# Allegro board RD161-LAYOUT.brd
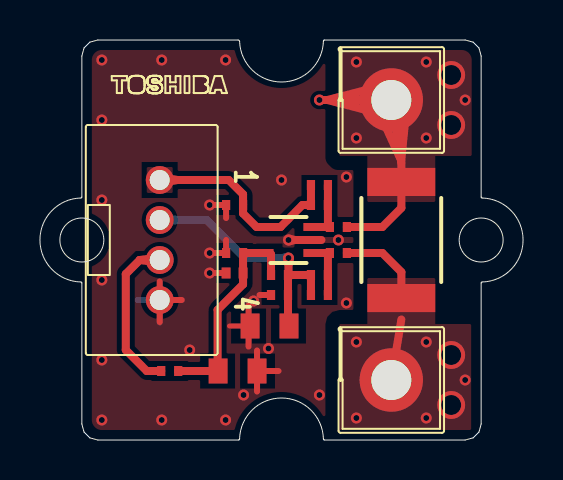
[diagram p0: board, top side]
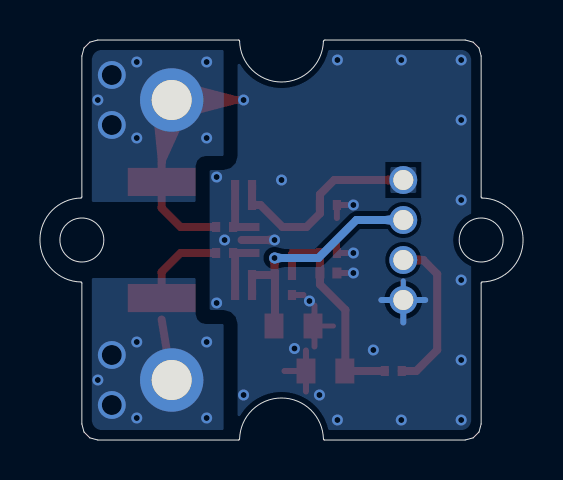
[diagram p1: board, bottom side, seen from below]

Outline 24.2 x 20 mm; copper layers: TOP, BOTTOM. Coordinates in mm from the lower left corner of the outline.
Outline path: circle c2.1,10 r1.1 ; circle c22.1,10 r1.1 ; 2.05,12.1 2.09,12.11 2.1,12.15 2.1,19.2 2.21,19.6 2.5,19.89 2.9,20 9.92,20 9.98,19.98 10,19.93 arc(12.11,17.9) 14.2,19.95 14.21,19.99 14.25,20 21.3,20 21.7,19.89 21.99,19.6 22.1,19.2 22.1,12.15 22.11,12.11 22.15,12.1 arc(24.2,10) 22.15,7.9 22.11,7.89 22.1,7.85 22.1,0.8 21.99,0.4 21.7,0.11 21.3,0 14.25,0 14.21,0.01 14.2,0.05 arc(12.1,2.1) 10,0.05 9.99,0.01 9.95,0 2.9,0 2.5,0.11 2.21,0.4 2.1,0.8 2.1,7.85 2.09,7.89 2.05,7.9 arc(0,10) 2.05,12.1

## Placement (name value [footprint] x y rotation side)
C1  -  [KC00050ACP]  14 7.25 180 top
C4  -  [KC01320AKP]  9.75 8.35 180 top
C5  -  [KC00050ACP]  9.75 9.35 180 top
C12  -  [KC00060ATP]  9.9 3.45 0 top
C13  -  [KC00050ACP]  14 12.75 180 top
C14  -  [KC00060ATP]  11.5 5.7 180 top
CN1  -  [CUP10060ATP]  6 13 270 top
NOREF  -  []  2.75 16.5 0 top
R1  -  [DR824K0ACP]  14 8.25 180 top
R9  -  [KC00050ACP]  6.5 3.45 180 top
R10  -  [R8100A]  18.1 10 90 top
R11  -  [DR824K0ACP]  14.95 9.35 180 top
R12  -  [DR824K0ACP]  14.95 10.65 180 top
R13  -  [DR824K0ACP]  14 11.75 180 top
R14  -  [DR824K0ACP]  12 7.25 180 top
R15  -  [DR824K0ACP]  12 8.25 180 top
R16  -  [KC00050ACP]  9.75 11.75 0 top
TP1  -  [DE051A]  17.6 3 0 top
TP2  -  [DE051A]  17.6 17 0 top
U1  -  [MM00380ACP]  12.45 10 90 top

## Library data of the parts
C1 C13 = GDM030000385: alternate symbols: (T:KC00050ACP;B:KC00050BCP)
C4 = GAS030000012: alternate symbols: (T:KC01320AKP;B:KC01320BKP)
C5 = GDM030002515: alternate symbols: (T:KC00050ACP;B:KC00050BCP)
C12 C14 = GDM030002136: alternate symbols: (T:KC00060ATP;B:KC00060BTP)
CN1 = K22S001P: alternate symbols: (T:CUP10060ATP;B:CUP10060BTP)
R1 R13 = G36010118152: alternate symbols: (T:DR824K0ACP;B:DR824K0BCP)
R9 R16 = GDM010000374: alternate symbols: (T:KC00050ACP;B:KC00050BCP)
R10 = K0100130: alternate symbols: (T:R8100A;B:R9100A)
R11 R12 = GDM010000088: alternate symbols: (T:DR824K0ACP;B:DR824K0BCP)
R14 = G36010118534: alternate symbols: (T:DR824K0ACP;B:DR824K0BCP)
R15 = G36010118602: alternate symbols: (T:DR824K0ACP;B:DR824K0BCP)
TP1 TP2 = ZS_DE051A: alternate symbols: (T:DE051A;B:NO_DE051A)
U1 = K47S002A: alternate symbols: (T:MM00380ACP;B:MM00380BCP)

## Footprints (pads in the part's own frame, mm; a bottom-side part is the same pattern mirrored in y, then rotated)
CUP10060ATP
  round 1.397 hole 1: 1(0,0) 2(2,0) 3(4,0) 4(6,0)
DE051A
  round 3.175 hole 2: 1(0,0)
DR824K0ACP
  rect 0.41x0.5 smd: 1(-0.425,0) 2(0.425,0)
KC00050ACP
  rect 0.41x0.5 smd: 1(-0.425,0) 2(0.425,0)
KC00060ATP
  rect 0.95x1.25 smd: 1(-0.975,0) 2(0.975,0)
KC01320AKP
  rect 0.45x0.55 smd: 1(-0.425,0) 2(0.425,0)
MM00380ACP
  rect 0.4x0.55 smd: 1(-0.65,-1.025) 2(0,-1.025) 3(0.65,-1.025) 4(0.65,1.025) 5(-0.65,1.025)
R8100A
  rect 1.405x3.4 smd: 1(-2.902,0) 2(2.902,0)

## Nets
GND: C4.2(TP-1) C5.2(TP-1) C12.2(TP-1) C14.2(TP-1) CN1.4 R10.2(TP-1) R12.1(TP-1) R14.2(TP-1) R16.1(TP-1) TP2.1 U1.2
SIG66: C13.1(TP-1) R12.2(TP-1) R13.1(TP-1) U1.3
SIG68: C1.1(TP-1) R1.1(TP-1) R11.2(TP-1) U1.1
SIG70: C1.2(TP-1) C14.1(TP-1) CN1.2 R1.2(TP-1) R14.1(TP-1) R15.1(TP-1)
SIG71: CN1.3 R9.2(TP-1)
SIG73: C4.1(TP-1) C5.1(TP-1) C12.1(TP-1) R9.1(TP-1) R15.2(TP-1) U1.5
SIG74: C13.2(TP-1) CN1.1 R13.2(TP-1) R16.2(TP-1) U1.4
SIG75: R10.1(TP-1) R11.1(TP-1) TP1.1

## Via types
v1: diameter 1.397, hole 1, TOP to BOTTOM, 4 vias
v2: diameter 0.55, hole 0.3, TOP to BOTTOM, 35 vias

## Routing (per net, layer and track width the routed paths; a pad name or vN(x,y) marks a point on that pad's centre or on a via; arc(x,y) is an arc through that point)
GND: length 46.3
  TOP w0.25: 9.5,5.7 C14.2
  TOP w0.3: C12.2 10.87,2.42 ; C12.2 11.95,3.45 ; C12.2 10.87,4.47 ; CN1.4 7.1,7 ; CN1.4 6,5.9 ; CN1.4 6,7.92 ; 10.45,6.72 10.45,5.78 C14.2 ; v2(8.5,11.75) R16.1 9.32,11.1 ; 10.45,4.67 10.45,5.7 ; 8.7,9.35 C5.2 9.32,10 ; C4.2 8.7,8.35 ; R14.2 11,7.25
  TOP w0.4: 14.4,17 17.4,16.22 ; 14.4,17 v2(14,17) ; 14.4,17 17.53,17 17.53,17.02 ; 14.4,17 17.4,17.77 ; R12.1 17.15,10.65 18.1,11.6 18.1,13.85 TP2.1 ; 18.1,13.97 18.06,16.86 ; 18.1,13.97 16.87,16.66 ; 18.1,13.97 18.4,16.92 ; v2(12.45,10) U1.2 14.1,10
  BOTTOM w0.25: CN1.4 6,7.95
  BOTTOM w0.3: 6,5.88 CN1.4 ; CN1.4 4.9,7 ; CN1.4 7.1,7
  vias: v1(20.6,18.25) v1(20.6,15.75) v2(3.1,19) v2(3.1,16) v2(3.1,12) v2(3.1,8) v2(3.1,4) v2(3.1,1) v2(6.1,19) v2(6.1,1) v2(7.5,4.5) v2(8.5,9.35) v2(8.5,8.35) v2(9.3,19) v2(9.3,1) v2(10.2,2.25) v2(10.7,6.95) v2(11.45,4.58) v2(12.1,13) v2(14,2.25) v2(14.95,10) v2(15.35,13.15) v2(15.35,6.85) v2(15.85,18.9) v2(15.85,15.1) v2(19.35,18.9) v2(19.35,15.1) v2(21.3,17)
SIG66: length 3.2
  TOP w0.4: 13.49,10.65 R12.2 14.42,10.75 R13.1 C13.1
SIG68: length 3.2
  TOP w0.4: 13.49,9.35 R11.2 14.42,9.25 R1.1 C1.1
SIG70: length 14.8
  TOP w0.4: R15.1 12.42,8.3 12.45,8.32 v2(12.45,9.1) ; R15.1 R14.1 12.42,5.75 C14.1 ; R15.1 R1.2 C1.2
  BOTTOM w0.4: 6.9,11 8.35,11 10.25,9.1 v2(12.45,9.1) ; 6.9,11 6.02,11.12 CN1.2 ; 6.9,11 6.02,10.88 CN1.2 ; 6.9,11 CN1.2
SIG71: length 10.2
  TOP w0.4: 5,9 5.97,9.12 CN1.3 ; 5,9 CN1.3 ; 5,9 5.97,8.88 CN1.3 ; 5,9 4.3,8.3 4.3,4.5 5.35,3.45 R9.2
SIG73: length 10.9
  TOP w0.4: 8.9,3.48 8.9,6.51 10.17,7.78 C4.1 C5.1 U1.5 11.51,9.35 11.57,9.29 R15.2 ; R9.1 C12.1
SIG74: length 12.5
  TOP w0.4: C13.2 R13.2 13.15,11.75 12.05,10.65 U1.4 10.85,10.65 10.17,11.32 R16.2 10.17,12.28 9.46,13 6.9,13 ; CN1.1 6.12,13.12 6.9,13 ; CN1.1 6.12,12.88 6.9,13 ; CN1.1 6.9,13
SIG75: length 7.6
  TOP w0.4: R11.1 17.15,9.35 18.1,8.4 18.1,7 ; TP1.1 18.1,6.02
  vias: v1(20.6,4.25) v1(20.6,1.75) v2(15.85,4.9) v2(15.85,1.1) v2(19.35,4.9) v2(19.35,1.1) v2(21.3,3)

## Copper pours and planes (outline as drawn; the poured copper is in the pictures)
GND on TOP: outline of 253 points within 2.6,0.5 15.7,19.5 ; 3 cut-outs
GND on TOP: 14.12,9.85 14.07,9.87 14.05,9.93 14.05,10.07 14.07,10.13 14.12,10.15 15.62,10.15 15.68,10.13 15.7,10.07 15.7,9.93 15.68,9.87 15.62,9.85
GND on BOTTOM: 2.6,8.64 2.61,8.68 2.65,8.71 3.5,10 2.65,11.29 2.61,11.32 2.6,11.36 2.6,19 2.75,19.35 3.1,19.5 9.69,19.5 9.72,19.49 9.75,19.48 9.76,19.46 9.77,19.44 11.74,17.63 14.16,18.77 14.17,18.78 14.24,18.8 14.3,18.75 14.3,18.73 14.3,14.2 14.39,13.85 14.65,13.59 15,13.5 15.62,13.5 15.68,13.48 15.7,13.43 15.7,6.58 15.68,6.52 15.62,6.5 15,6.5 14.65,6.41 14.39,6.15 14.3,5.8 14.3,1.27 14.3,1.25 14.24,1.2 14.17,1.22 14.16,1.23 12.4,2.38 10.4,1.7 10.01,1.17 9.77,0.56 9.75,0.53 9.73,0.51 9.71,0.5 9.69,0.5 3.1,0.5 2.75,0.65 2.6,1 ; 4 cut-outs
SIG74 on TOP, BOTTOM: 5.42,12.35 5.37,12.37 5.35,12.43 5.35,13.57 5.37,13.63 5.42,13.65 6.57,13.65 6.63,13.63 6.65,13.57 6.65,12.43 6.63,12.37 6.57,12.35

Small or netless copper shapes (teardrops, artwork), in the pictures only: 4 on TOP, 3 on BOTTOM

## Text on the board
Ref Des/Silkscreen Top: 1 | 4
SYMBOL-1-TOP: 1 | 4
SYMBOL-2-TOP: Low(-) | Hi(+) | CN1 | R9 | C12 | R16 | C5 | C4 | U1 | R15 | R14 | C13 | R13 | R1 | C1 | C14 | R12 | R11 | R10 | 1
User.9: Vcc | Gnd | Out | Bia | Low | GROVE-C | Hi
